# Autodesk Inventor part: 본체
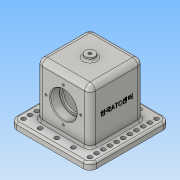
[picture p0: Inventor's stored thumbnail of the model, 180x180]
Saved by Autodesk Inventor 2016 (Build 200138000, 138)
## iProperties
Created: 2018-11
Part Number: 본체
Material: 알루미늄 6061
Document SubType Name: Modeling
Designer: Administrator
Density: 2.7 g/cm^3
Appearance: 알루미늄 - 평지
Mass: 1016.99 g
Surface Area: 777.082 cm^2
Volume: 376.663 cm^3
Author: Administrator
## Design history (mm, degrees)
sketch "스케치1"
  geometry: L1 (40, 40)-(-40, 40); L2 (-40, 40)-(-40, -40); L3 (-40, -40)-(40, -40); L4 (40, -40)-(40, 40); L5 (40, 40)-(-40, -40); L6 (-40, 40)-(40, -40); 1 further point
  constraints: 12 end point, 2 midpoint, 2 parallel, 1 horizontal, 1 perpendicular
  dimensions: "d0" = 80 distance of L3.end L2.end; "d1" = 80 distance of L2.end L1.end
extrude "돌출1" new body sketch "스케치1" stored distance "d2" = 80; taper "d3" = 0 deg
sketch "스케치2"
  geometry: L1 (100, -100)-(-20, -100); L2 (-20, -100)-(-20, 20); L3 (-20, 20)-(100, 20); L4 (100, 20)-(100, -100); L5 (100, -100)-(-20, 20); L6 (-20, -100)-(100, 20); 1 further point
  constraints: 12 end point, 2 midpoint, 2 parallel, 1 horizontal, 1 perpendicular
  dimensions: "d4" = 120 distance of L2.end L3.end; "d5" = 120 distance of L1.end L2.end
extrude "돌출2" join sketch "스케치2" distance "d6" = 10; taper "d7" = 0 deg
feature "쉘1" dims "d8" = 10, "d9" = 17, "d58" = 10
sketch "스케치3"
  geometry: L1 (30, -50)-(-30, -50) reference; L2 (0, -50)-(0, -2); C1 r 20 at (0, -2); 1 further point
  constraints: 2 end point, 1 centre point, 1 coincident, 1 midpoint, 1 vertical
  dimensions: "d10" = 48 distance of L2.start L2.end; "d11" = 40 diameter of C1
extrude "돌출3" cut sketch "스케치3" distance "d12" = 14; taper "d13" = 0 deg
sketch "스케치4"
  geometry: C1 r 20 at (0, 0) reference; C2 r 20 at (0, 0) reference; C3 r 16.5 at (0, 0); 1 further point
  constraints: 1 centre point, 1 coincident
  dimensions: "d14" = 33 diameter of C3
extrude "돌출4" cut sketch "스케치4" distance "d15" = 3; taper "d16" = 0 deg
node "작업 평면1"
sketch "스케치5"
  geometry: C1 r 7.5 at (40, -40); 1 further point
  constraints: 1 centre point, 1 coincident
  dimensions: "d18" = 15 diameter of C1
extrude "돌출5" join sketch "스케치5" stored distance "d19" = 3; taper "d20" = 0 deg
hole "구멍1" diameter "d23" = 4.917; stored, may be unused: countersink angle "d27" = 90 deg, drill point angle "d29" = 118 deg; dims "d21" = 10, "d22" = 10, "d24" = 12, "d25" = 4, "d26" = 2, "d28" = 17.1
sketch "스케치6"
  geometry: L1 (0, -2)-(0, 24); C1 r 16.5 at (0, -2) reference; 2 further points
  constraints: 2 end point, 1 coincident, 1 vertical
  dimensions: "d30" = 26 distance of L1.start L1.end
hole "구멍2" sketch "스케치6" at (0, 24) diameter "d31" = 3.242; stored, may be unused: countersink angle "d35" = 90 deg, drill point angle "d37" = 118 deg; dims "d32" = 8, "d33" = 4, "d34" = 2, "d36" = 10
sketch "스케치7"
  geometry: L1 (0, 2)-(0, -24); C1 r 16.5 at (0, 2) reference; C2 r 1.621 at (0, -24) reference; 2 further points
  constraints: 2 end point, 1 coincident, 1 vertical
  dimensions: "d41" = 26 distance of L1.start L1.end (derived)
hole "구멍3" sketch "스케치7" at (0, -24) diameter "d42" = 3.242; stored, may be unused: countersink angle "d46" = 90 deg, drill point angle "d48" = 118 deg; dims "d43" = 8, "d44" = 4, "d45" = 2, "d47" = 10
chamfer "모따기1" distance "d52" = 1; stored, may be unused: second distance "d53" = 2, angle "d54" = 45 deg
fillet "모깎기1" dims "d55" = 8
fillet "모깎기2" dims "d56" = 8
fillet "모깎기3" dims "d57" = 0.6
fillet "모깎기4" dims "d59" = 3
fillet "모깎기5" dims "d60" = 3
fillet "모깎기6" dims "d61" = 10
fillet "모깎기7" dims "d62" = 3
hole "구멍4" diameter "d65" = 6.6; stored, may be unused: countersink angle "d69" = 90 deg, drill point angle "d71" = 118 deg; dims "d63" = 10, "d64" = 10, "d66" = 8, "d67" = 4, "d68" = 2, "d70" = 10
hole "구멍5" diameter "d74" = 6.6; stored, may be unused: countersink angle "d78" = 90 deg, drill point angle "d80" = 118 deg; dims "d72" = 10, "d73" = 10, "d75" = 8, "d76" = 4, "d77" = 2, "d79" = 10
hole "구멍6" diameter "d83" = 6.6; stored, may be unused: countersink angle "d87" = 90 deg, drill point angle "d89" = 118 deg; dims "d81" = 10, "d82" = 10, "d84" = 8, "d85" = 4, "d86" = 2, "d88" = 10
hole "구멍7" diameter "d92" = 6.6; stored, may be unused: countersink angle "d96" = 90 deg, drill point angle "d98" = 118 deg; dims "d90" = 10, "d91" = 10, "d93" = 8, "d94" = 4, "d95" = 2, "d97" = 10
sketch "스케치8" dims "d107" = 10, "d111" = 10
  geometry: L1 (-90, -90)-(-90, 10); L2 (-90, 20)-(10, 20) reference; L3 (-90, -90)-(10, -90); L4 (-40, -40)-(-48.489, -40); L5 (-40, -40)-(-40, -32.862); L6 (10, -90)-(10, 10); C1 r 3.3 at (-90, -90) reference; C2 r 3.3 at (-90, 10) reference; C3 r 3.3 at (10, -90) reference; C4 r 3.3 at (10, 10) reference; C5 r 3.3 at (-90, 10) reference; C6 r 3.3 at (10, -90); C7 r 3.3 at (10, 10); C8 r 3.3 at (10, 10); 27 further points
  constraints: 15 symmetric about line, 10 end point, 3 centre point, 3 horizontal, 2 coincident, 2 vertical, 1 perpendicular, 16 other
  dimensions: "d99" = 100 distance of L1.start L1.end (derived); "d101" = 100 distance of L1.start L3.end (derived); "d104" = 10 distance of point (-90, -90) point (-90, -80); "d114" = 25 distance of point (-90, -90) point (-65, -90)
hole "구멍8" sketch "스케치8" diameter "d116" = 6.6; stored, may be unused: countersink angle "d120" = 90 deg, drill point angle "d122" = 118 deg; dims "d117" = 8, "d118" = 4, "d119" = 2, "d121" = 10
sketch "스케치9"
  geometry: L1 (82, 82)-(82, -18) reference; 2 further points
  constraints: 1 horizontal alignment, 1 other
  dimensions: "d123" = 48 distance from line of L1 point (34, 32)
feature "엠보싱1" sketch "스케치9" dims "d0" = 80, "d1" = 80, "d124" = 0.5, "d125" = 0
node "솔리드1"
mirror "대칭1"
pattern_circular "원형 패턴1" dims angle "d39" = 360 deg
pattern_circular "원형 패턴2" dims angle "d50" = 360 deg
node "투영된 루프1"
other parameters: "d17" = 5
